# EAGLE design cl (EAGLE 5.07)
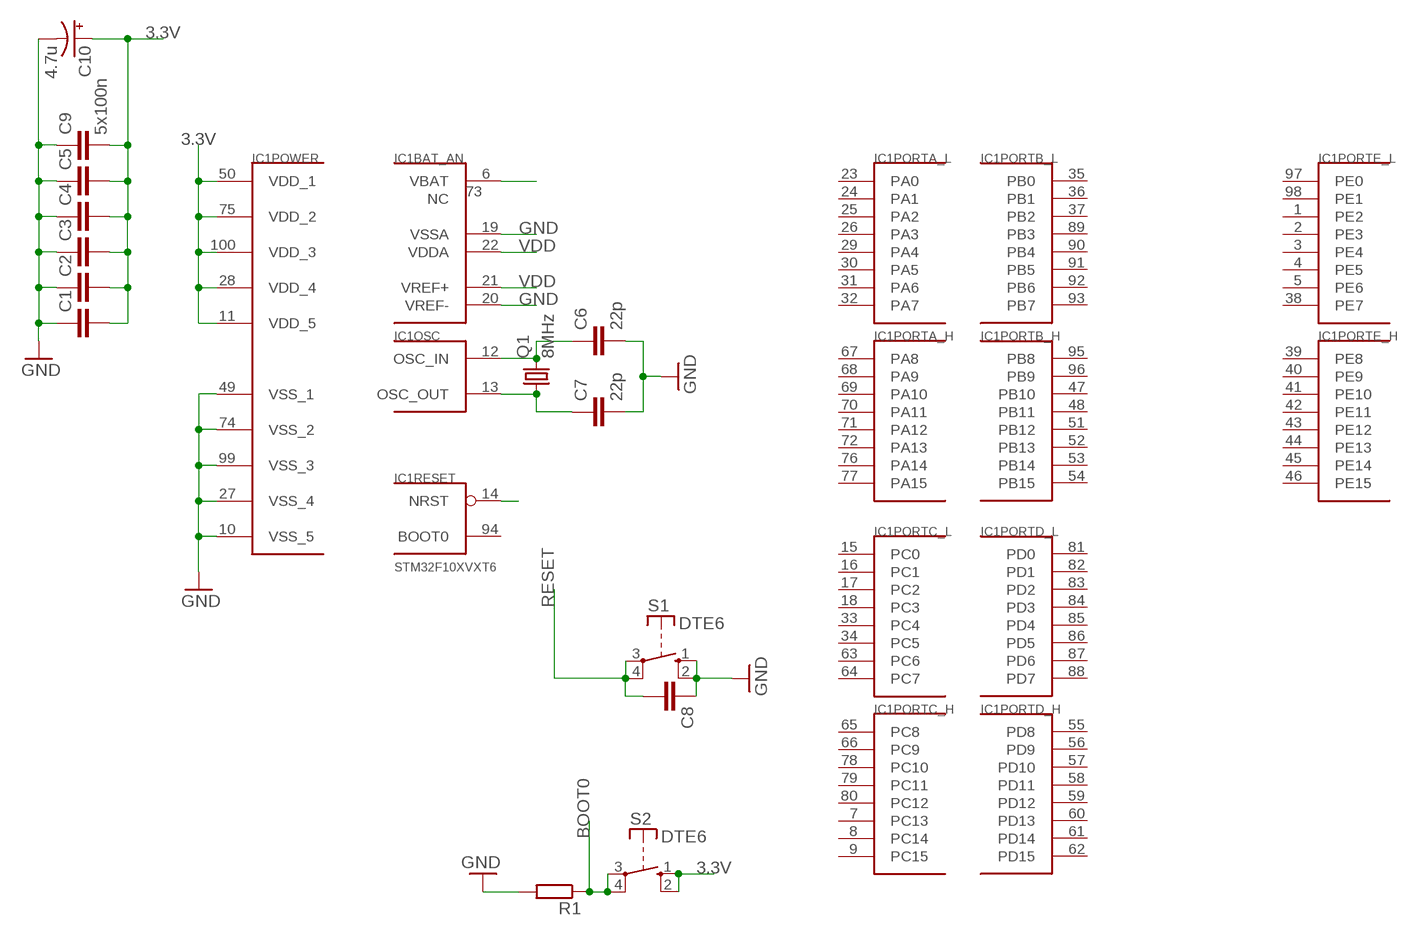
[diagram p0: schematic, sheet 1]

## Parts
C1  C-EUC0805K  [C0805K]
C2  C-EUC0805K  [C0805K]
C3  C-EUC0805K  [C0805K]
C4  C-EUC0805K  [C0805K]
C5  C-EUC0805K  [C0805K]
C6  22p  C-EUC0805K  [C0805K]
C7  22p  C-EUC0805K  [C0805K]
C8  C-EUC0805K  [C0805K]
C9  5x100n  C-EUC0805K  [C0805K]
C10  4.7u  CPOL-USE3.5-8  [E3,5-8]
IC1  STM32F10XVXT6  [TQFP100]
Q1  8MHz  CRYSTALHC49S  [HC49/S]
R1  R-EU_R0805  [R0805]
S1  DTE6  [DTE6]
S2  DTE6  [DTE6]

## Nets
3.3V: C1.2 C2.2 C3.2 C4.2 C5.2 C9.2 C10.+ IC1.11(POWER:VDD_5) IC1.28(POWER:VDD_4) IC1.50(POWER:VDD_1) IC1.75(POWER:VDD_2) IC1.100(POWER:VDD_3) S2.1(S) S2.2(S)
BOOT0: R1.1 S2.3(P) S2.4(P)
GND: C1.1 C2.1 C3.1 C4.1 C5.1 C6.2 C7.2 C8.1 C9.1 C10.- IC1.10(POWER:VSS_5) IC1.19(BAT_AN:VSSA) IC1.20(BAT_AN:VREF-) IC1.27(POWER:VSS_4) IC1.49(POWER:VSS_1) IC1.74(POWER:VSS_2) IC1.99(POWER:VSS_3) R1.2 S1.1(S) S1.2(S)
N$1: IC1.6(BAT_AN:VBAT)
N$2: IC1.14(RESET:NRST)
N$8: C7.1 IC1.13(OSC:OSC_OUT) Q1.1
N$9: C6.1 IC1.12(OSC:OSC_IN) Q1.2
RESET: C8.2 S1.3(P) S1.4(P)
VDD: IC1.21(BAT_AN:VREF+) IC1.22(BAT_AN:VDDA)
Unconnected: IC1.1(PORTE_L:PE2) IC1.2(PORTE_L:PE3) IC1.3(PORTE_L:PE4) IC1.4(PORTE_L:PE5) IC1.5(PORTE_L:PE6) IC1.7(PORTC_H:PC13) IC1.8(PORTC_H:PC14) IC1.9(PORTC_H:PC15) IC1.15(PORTC_L:PC0) IC1.16(PORTC_L:PC1) IC1.17(PORTC_L:PC2) IC1.18(PORTC_L:PC3) IC1.23(PORTA_L:PA0) IC1.24(PORTA_L:PA1) IC1.25(PORTA_L:PA2) IC1.26(PORTA_L:PA3) IC1.29(PORTA_L:PA4) IC1.30(PORTA_L:PA5) IC1.31(PORTA_L:PA6) IC1.32(PORTA_L:PA7) IC1.33(PORTC_L:PC4) IC1.34(PORTC_L:PC5) IC1.35(PORTB_L:PB0) IC1.36(PORTB_L:PB1) IC1.37(PORTB_L:PB2) IC1.38(PORTE_L:PE7) IC1.39(PORTE_H:PE8) IC1.40(PORTE_H:PE9) IC1.41(PORTE_H:PE10) IC1.42(PORTE_H:PE11) IC1.43(PORTE_H:PE12) IC1.44(PORTE_H:PE13) IC1.45(PORTE_H:PE14) IC1.46(PORTE_H:PE15) IC1.47(PORTB_H:PB10) IC1.48(PORTB_H:PB11) IC1.51(PORTB_H:PB12) IC1.52(PORTB_H:PB13) IC1.53(PORTB_H:PB14) IC1.54(PORTB_H:PB15) IC1.55(PORTD_H:PD8) IC1.56(PORTD_H:PD9) IC1.57(PORTD_H:PD10) IC1.58(PORTD_H:PD11) IC1.59(PORTD_H:PD12) IC1.60(PORTD_H:PD13) IC1.61(PORTD_H:PD14) IC1.62(PORTD_H:PD15) IC1.63(PORTC_L:PC6) IC1.64(PORTC_L:PC7) IC1.65(PORTC_H:PC8) IC1.66(PORTC_H:PC9) IC1.67(PORTA_H:PA8) IC1.68(PORTA_H:PA9) IC1.69(PORTA_H:PA10) IC1.70(PORTA_H:PA11) IC1.71(PORTA_H:PA12) IC1.72(PORTA_H:PA13) IC1.73(BAT_AN:NC) IC1.76(PORTA_H:PA14) IC1.77(PORTA_H:PA15) IC1.78(PORTC_H:PC10) IC1.79(PORTC_H:PC11) IC1.80(PORTC_H:PC12) IC1.81(PORTD_L:PD0) IC1.82(PORTD_L:PD1) IC1.83(PORTD_L:PD2) IC1.84(PORTD_L:PD3) IC1.85(PORTD_L:PD4) IC1.86(PORTD_L:PD5) IC1.87(PORTD_L:PD6) IC1.88(PORTD_L:PD7) IC1.89(PORTB_L:PB3) IC1.90(PORTB_L:PB4) IC1.91(PORTB_L:PB5) IC1.92(PORTB_L:PB6) IC1.93(PORTB_L:PB7) IC1.94(RESET:BOOT0) IC1.95(PORTB_H:PB8) IC1.96(PORTB_H:PB9) IC1.97(PORTE_L:PE0) IC1.98(PORTE_L:PE1)

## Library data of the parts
C1-C9 = resistor:C-EU: CAPACITOR, European symbol
C10 = resistor:CPOL-US: POLARIZED CAPACITOR, American symbol
IC1 = stm32:STM32F10XVXT6: STM32F101/103 100 pin LQFP
Q1 = crystal:CRYSTAL: CRYSTAL
R1 = resistor:R-EU_: RESISTOR, European symbol
S1 S2 = switch-misc:DT: ITT SWITCH

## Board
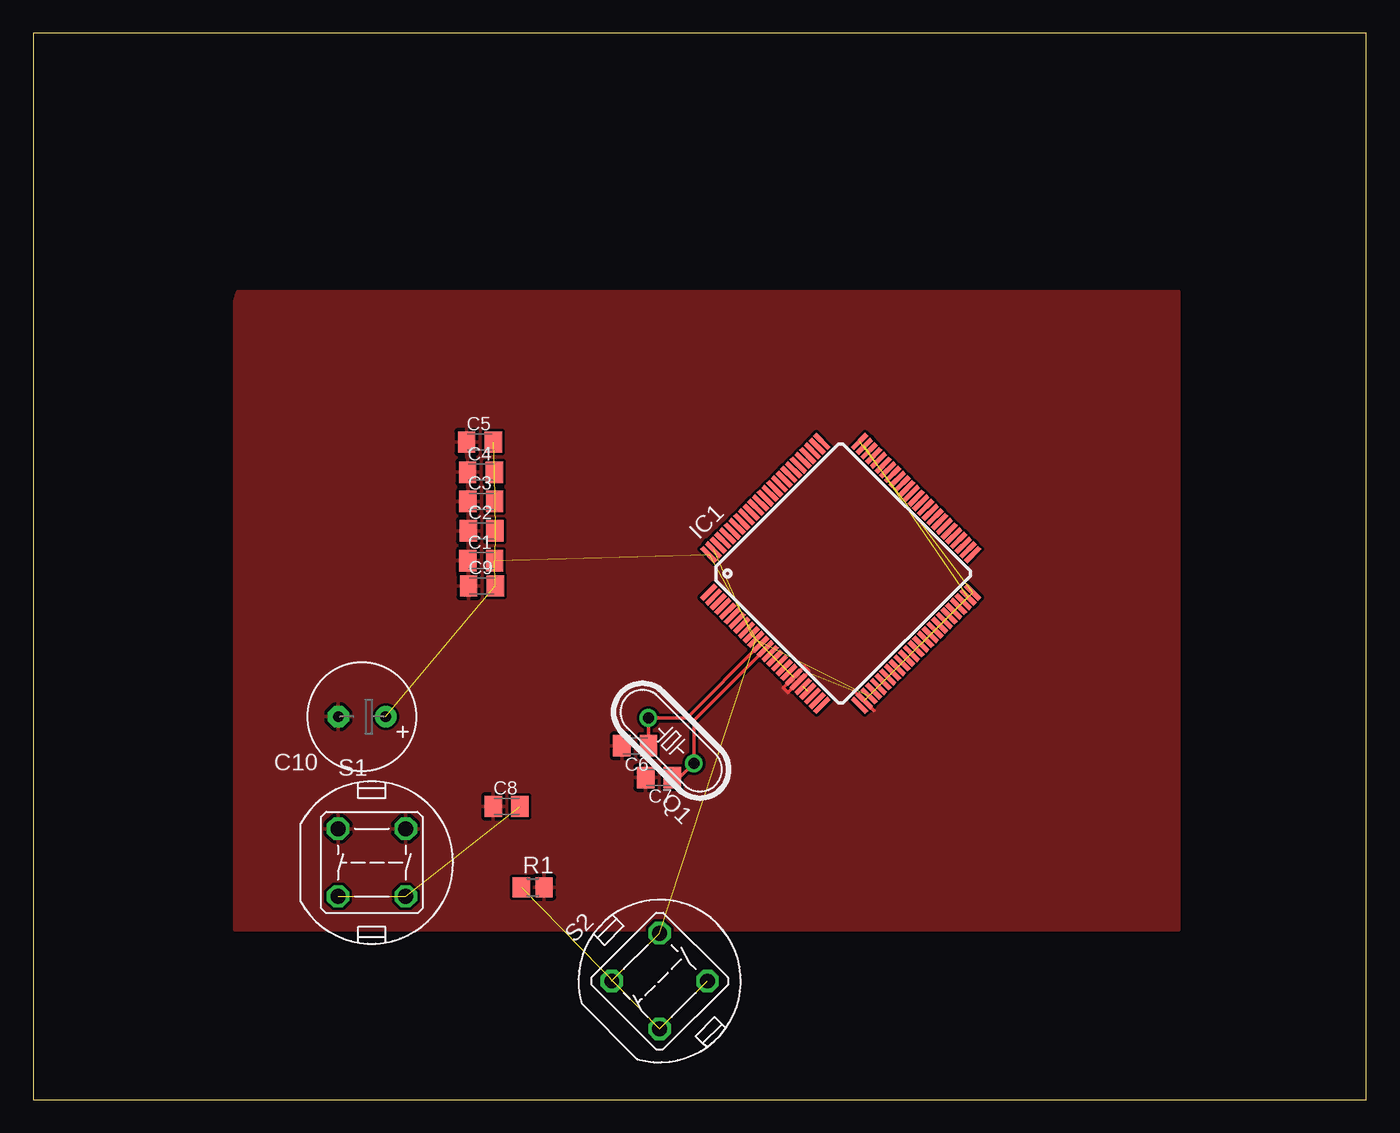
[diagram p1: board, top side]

Size 100 x 80 mm. Coordinates in mm from the lower left corner, seen from the top.
Outline: 0,0 100,0 100,80 0,80 0,0
Copper layers (1*16): Top 0.035mm / dielectric 1.5mm / Bottom 0.035mm
Design rules "default": minimum track width 10mil, minimum drill 24mil, track to track 8mil, track to pad 8mil, pad to pad 8mil, via to via 8mil, smd to smd 8mil, copper to edge 40mil, drill to drill 8mil, minimum pad ring 10mil, minimum via ring 8mil, stop-mask expansion 4mil, vias tented up to drill 0mil, thermal gap 10mil

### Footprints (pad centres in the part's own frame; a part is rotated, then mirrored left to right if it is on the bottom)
C0805K = smd 1.3 x 1.6: 1 -1,0; 2 1,0
E3,5-8 = drill 0.813 pad 1.6 round: + -1.778,0 | drill 0.813 pad 1.6 octagon: - 1.778,0
TQFP100 = smd 1.5 x 0.35: 1 -8,6; 2 -8,5.5; 3 -8,5; 4 -8,4.5; 5 -8,4; 6 -8,3.5; 7 -8,3; 8 -8,2.5; 9 -8,2; 10 -8,1.5; 11 -8,1; 12 -8,0.5; 13 -8,0; 14 -8,-0.5; 15 -8,-1; 16 -8,-1.5; 17 -8,-2; 18 -8,-2.5; 19 -8,-3; 20 -8,-3.5; 21 -8,-4; 22 -8,-4.5; 23 -8,-5; 24 -8,-5.5; 25 -8,-6; 51 8,-6; 52 8,-5.5; 53 8,-5; 54 8,-4.5; 55 8,-4; 56 8,-3.5; 57 8,-3; 58 8,-2.5; 59 8,-2; 60 8,-1.5; 61 8,-1; 62 8,-0.5; 63 8,0; 64 8,0.5; 65 8,1; 66 8,1.5; 67 8,2; 68 8,2.5; 69 8,3; 70 8,3.5; 71 8,4; 72 8,4.5; 73 8,5; 74 8,5.5; 75 8,6 | smd 0.35 x 1.5: 26 -6,-8; 27 -5.5,-8; 28 -5,-8; 29 -4.5,-8; 30 -4,-8; 31 -3.5,-8; 32 -3,-8; 33 -2.5,-8; 34 -2,-8; 35 -1.5,-8; 36 -1,-8; 37 -0.5,-8; 38 0,-8; 39 0.5,-8; 40 1,-8; 41 1.5,-8; 42 2,-8; 43 2.5,-8; 44 3,-8; 45 3.5,-8; 46 4,-8; 47 4.5,-8; 48 5,-8; 49 5.5,-8; 50 6,-8; 76 6,8; 77 5.5,8; 78 5,8; 79 4.5,8; 80 4,8; 81 3.5,8; 82 3,8; 83 2.5,8; 84 2,8; 85 1.5,8; 86 1,8; 87 0.5,8; 88 0,8; 89 -0.5,8; 90 -1,8; 91 -1.5,8; 92 -2,8; 93 -2.5,8; 94 -3,8; 95 -3.5,8; 96 -4,8; 97 -4.5,8; 98 -5,8; 99 -5.5,8; 100 -6,8
HC49/S = drill 0.813 round: 1 -2.413,0; 2 2.413,0
R0805 = smd 1.3 x 1.5: 1 -0.85,0; 2 0.85,0
DTE6 = drill 1.118 octagon: 1 -2.54,2.54; 2 2.54,2.54; 3 2.54,-2.54; 4 -2.54,-2.54

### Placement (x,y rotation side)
C1  33.6,40.44 0 top
C2  33.63,42.67 0 top
C3  33.6,44.88 0 top
C4  33.58,47.07 0 top
C5  33.5,49.33 0 top
C6  45.16,26.54 180 top
C7  46.94,24.16 180 top
C8  35.51,22 0 top
C9  33.66,38.53 0 top
C10  24.66,28.73 180 top
IC1  60.58,39.47 45 top
Q1  47.85,26.92 135 top
R1  37.47,15.93 0 top
S1  25.4,17.78 0 top
S2  46.99,8.89 45 top

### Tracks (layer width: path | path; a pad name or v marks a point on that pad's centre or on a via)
3.3V  (13 unrouted)
BOOT0  (2 unrouted)
GND  (5 unrouted)
  Top 0.254: IC1.20 57.43,31.34 58.14,32.05 58.14,32.21 57.86,32.49 57.84,32.49 56.29,30.94 56.29,30.89 56.62,30.56 57.28,31.22 | IC1.27 63.07,29.21 63.04,29.21 61.54,30.71
  pour Top: 15.34,60.63 85.93,60.63 85.93,12.73 15.09,12.73 15.09,59.92
N$8
  Top 0.254: IC1.13 49.56,28.45 Q1.1 48.5,24.16 C7.1
N$9
  Top 0.254: IC1.12 49.03,28.63 Q1.2 46.16,28.62 C6.1
RESET  (2 unrouted)
VDD  (1 unrouted)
